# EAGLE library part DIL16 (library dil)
SOCKET Dual In Line
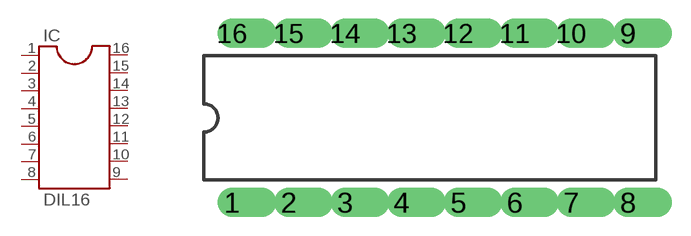
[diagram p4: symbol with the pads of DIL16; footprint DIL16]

Designator prefix IC

## DIL16  [DIL16]
1  1  pas
2  2  pas
3  3  pas
4  4  pas
5  5  pas
6  6  pas
7  7  pas
8  8  pas
9  9  pas
10  10  pas
11  11  pas
12  12  pas
13  13  pas
14  14  pas
15  15  pas
16  16  pas

## Footprint DIL16 (pad centres in mm)
SOCKET Dual In Line
drill 0.813 offset: 1 -8.89,-3.81; 2 -6.35,-3.81; 3 -3.81,-3.81; 4 -1.27,-3.81; 5 1.27,-3.81; 6 3.81,-3.81; 7 6.35,-3.81; 8 8.89,-3.81; 9 8.89,3.81; 10 6.35,3.81; 11 3.81,3.81; 12 1.27,3.81; 13 -1.27,3.81; 14 -3.81,3.81; 15 -6.35,3.81; 16 -8.89,3.81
